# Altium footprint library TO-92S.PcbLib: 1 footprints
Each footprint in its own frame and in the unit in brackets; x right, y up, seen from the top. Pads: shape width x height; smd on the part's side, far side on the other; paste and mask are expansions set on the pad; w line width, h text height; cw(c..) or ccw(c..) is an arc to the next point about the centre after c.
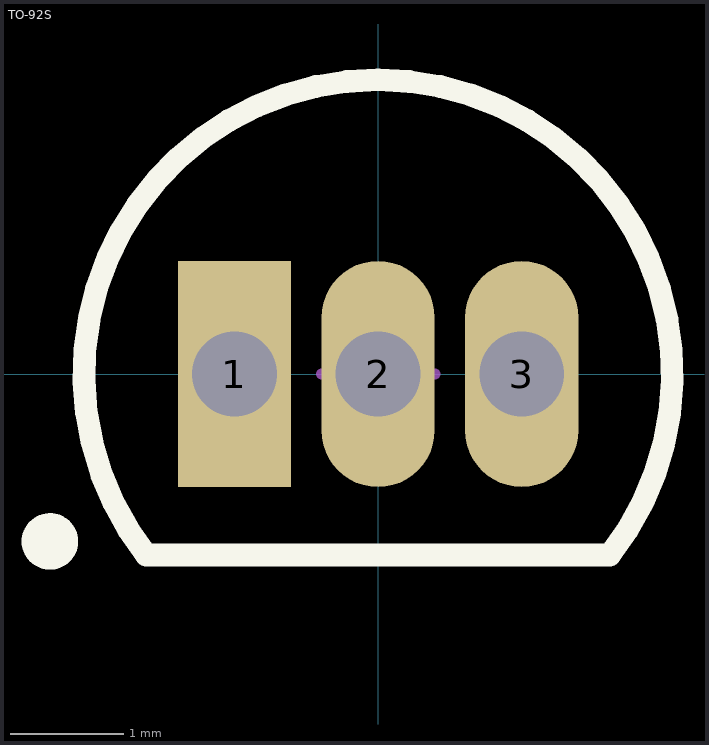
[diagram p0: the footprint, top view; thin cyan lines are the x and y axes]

## TO-92S [mm]
pads (3):
  rect 1x2 hole 0.75: 1(-1.27,0)
  oval 1x2 hole 0.75: 2(0,0) 3(1.27,0)
Top Overlay:
  circle w0.25: c-2.9,-1.48 r0.125
  lines w0.2: -2.049,-1.601 cw(c0,0) 2.049,-1.601 -2.049,-1.6
Mechanical 13:
  lines w0.1: -2.049,-1.601 cw(c0,0) 2.049,-1.601 -2.049,-1.6
Mechanical 15:
  lines w0.1: -0.5,0 0.5,0 ; 0,-0.5 0,0.5
3D body "User Library-TO-92A.STEP": height 8.5, standoff -2.5, extent -2.4,-1.53 2.4,2.4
